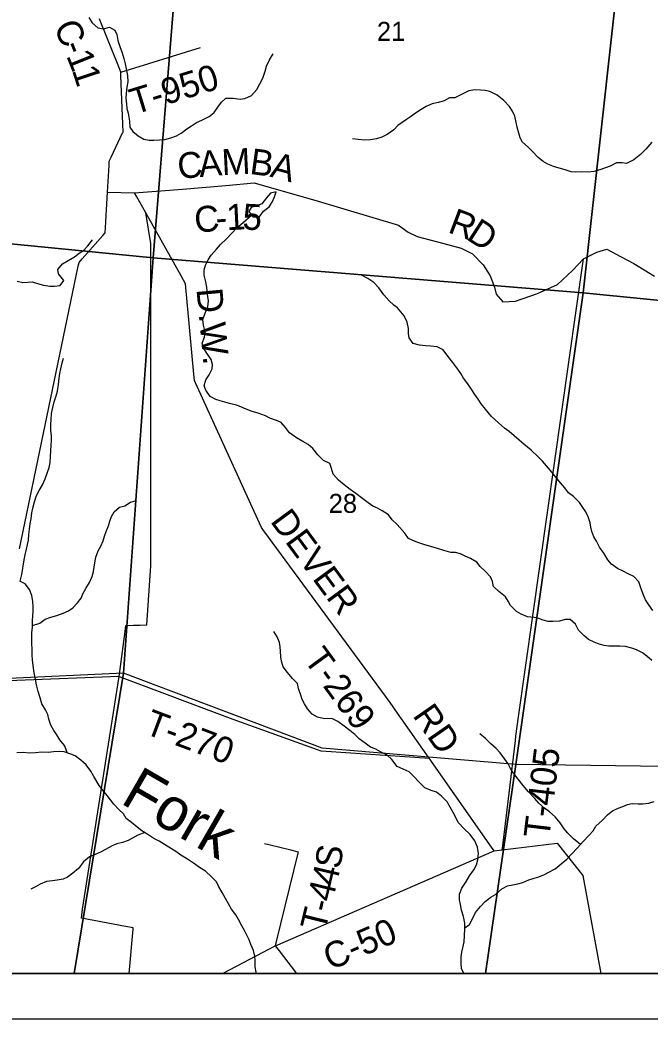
# Model space of a CAD drawing. Extents: x 0 to 34, y 0 to 22.
# Drawn here: x 27.818 to 29.202, y 14 to 16.193 of the extents above; entities that cross this region are included whole.
import ezdxf

# ---------------------------------------------------------------- set-up
doc = ezdxf.new("R2010")
doc.units = 0
for name, color, linetype in [('GM_X_Corporation', 7, 'Continuous'), ('GM_X_County_Road', 7, 'Continuous'), ('GM_X_County_Road_Text', 7, 'Continuous'), ('GM_X_Minor_Lake', 7, 'Continuous'), ('GM_X_Minor_River', 7, 'Continuous'), ('GM_X_Minor_River_Text', 7, 'Continuous'), ('GM_X_Section_Text', 7, 'Continuous'), ('GM_X_Township_Road', 7, 'Continuous'), ('GM_X_Township_Road_Text', 7, 'Continuous'), ('SH_Data', 7, 'Continuous')]:
    doc.layers.add(name, color=color, linetype=linetype)

msp = doc.modelspace()

# ---------------------------------------------------------------- linework, layer by layer
at = {"layer": 'GM_X_Corporation'}
msp.add_lwpolyline([(25.8273, 14.1), (30.3167, 14.1), (30.3167, 19.5906)], dxfattribs=at)
for points in [[(27.1145, 16.8163), (28.199, 16.7653), (28.1104, 15.671), (27.112, 15.7689)], [(29.176, 16.6858), (29.0551, 15.5941), (28.1104, 15.671), (28.199, 16.7653)], [(30.115, 16.6136), (29.9973, 15.5007), (29.0551, 15.5941), (29.176, 16.6858)], [(28.1104, 15.671), (28.0453, 14.7589), (27.0394, 14.7121), (27.112, 15.7689)], [(29.0551, 15.5941), (28.9075, 14.5584), (28.4817, 14.5947), (28.0453, 14.7589), (28.1104, 15.671)], [(29.9973, 15.5007), (29.8921, 14.5457), (28.9075, 14.5584), (29.0551, 15.5941)], [(26.9884, 14.1), (27.9368, 14.1), (28.0453, 14.7589), (27.0394, 14.7121)], [(27.9368, 14.1), (28.8409, 14.1), (28.9075, 14.5584), (28.4817, 14.5947), (28.0453, 14.7589)], [(28.8409, 14.1), (29.8452, 14.1), (29.8921, 14.5457), (28.9075, 14.5584)]]:
    msp.add_lwpolyline(points, close=True, dxfattribs=at)
at = {"layer": 'GM_X_County_Road'}
for points in [[(27.8173, 15.0322), (27.9461, 15.6525), (27.9478, 15.661), (27.9549, 15.669), (28.0002, 15.72), (28.0055, 15.726), (28.0061, 15.7375), (28.0105, 15.8154), (28.0137, 15.8738), (28.0142, 15.8832), (28.0185, 15.8922), (28.0436, 15.9451), (28.0446, 15.947), (28.0439, 15.9643), (28.0399, 16.0714), (28.0396, 16.0781), (28.0349, 16.09), (27.9953, 16.1896), (27.993, 16.1954)], [(28.0105, 15.8154), (28.0699, 15.8134), (28.1752, 15.8214), (28.27, 15.83), (28.3323, 15.8357), (28.4733, 15.7956), (28.6495, 15.7425), (28.6704, 15.7274), (28.6908, 15.718), (28.7492, 15.7024), (28.7874, 15.6923), (28.8121, 15.6799), (28.8356, 15.6558), (28.8508, 15.6312), (28.86, 15.6066), (28.8643, 15.5914), (28.8787, 15.5744), (28.9067, 15.5761), (28.955, 15.5926), (28.9985, 15.6126), (29.032, 15.6434), (29.0561, 15.6686), (29.0848, 15.6835), (29.1071, 15.6901), (29.1374, 15.6735), (29.1663, 15.6581), (29.2121, 15.6303)], [(28.0576, 14.1), (28.0667, 14.1974), (28.0669, 14.1999), (28.05, 14.2031), (27.953, 14.2215), (27.9558, 14.2408), (28.0358, 14.7517), (27.7925, 14.7425), (27.7824, 14.7421)], [(28.3792, 14.1607), (28.8594, 14.3689), (28.8774, 14.3711), (28.9977, 14.3857), (29.0546, 14.3151), (29.0938, 14.1)], [(28.4261, 14.1), (28.424, 14.1026), (28.3878, 14.1495), (28.3792, 14.1607), (28.3655, 14.1536), (28.2639, 14.1)]]:
    msp.add_lwpolyline(points, dxfattribs=at)
at = {"layer": 'GM_X_Minor_Lake'}
for points in [[(28.3773, 15.8045), (28.3811, 15.8156), (28.3682, 15.8126), (28.3595, 15.8028), (28.3496, 15.7896), (28.3375, 15.7851), (28.3261, 15.7813), (28.3208, 15.7723)], [(28.3208, 15.7723), (28.3298, 15.7612), (28.3434, 15.7604), (28.353, 15.7733), (28.3655, 15.7827), (28.3723, 15.7929), (28.3773, 15.8045)]]:
    msp.add_lwpolyline(points, dxfattribs=at)
at = {"layer": 'GM_X_Minor_River'}
for points in [[(27.9694, 16.1985), (27.9769, 16.1864), (27.9894, 16.1757), (28.0019, 16.1734), (28.0151, 16.1771), (28.0264, 16.1703), (28.0306, 16.1608), (28.0332, 16.1479), (28.0373, 16.1346), (28.0425, 16.1209), (28.0463, 16.1088), (28.0492, 16.097), (28.0522, 16.0822), (28.0544, 16.0708), (28.0548, 16.0576), (28.0528, 16.0455), (28.0516, 16.0318), (28.0509, 16.0223), (28.0519, 16.0083), (28.053, 15.9985), (28.0556, 15.9882), (28.0586, 15.9708), (28.0597, 15.9575), (28.0661, 15.948), (28.0778, 15.9388), (28.0899, 15.9316), (28.1016, 15.9293), (28.1122, 15.9289), (28.1243, 15.9299), (28.136, 15.931), (28.1493, 15.934), (28.1618, 15.9389), (28.172, 15.9445), (28.1849, 15.9544), (28.1951, 15.9604), (28.2061, 15.9679), (28.2179, 15.9732), (28.2338, 15.9811), (28.2444, 15.9901), (28.2528, 16.0019), (28.2604, 16.0124), (28.2706, 16.0211), (28.2862, 16.0211), (28.302, 16.0195), (28.3123, 16.0206), (28.3263, 16.0274), (28.3381, 16.0406), (28.3449, 16.0531), (28.3514, 16.0655), (28.3564, 16.0803), (28.3594, 16.092), (28.3659, 16.1053), (28.3739, 16.1189)], [(29.2058, 15.9247), (29.1929, 15.9092), (29.1807, 15.8975), (29.1667, 15.8862), (29.1504, 15.878), (29.1406, 15.8792), (29.1281, 15.8796), (29.1141, 15.8721), (29.0918, 15.8638), (29.0785, 15.8605), (29.0664, 15.859), (29.0521, 15.8598), (29.0392, 15.8591), (29.029, 15.8596), (29.0177, 15.863), (29.0056, 15.8669), (28.9924, 15.8707), (28.9777, 15.8765), (28.9675, 15.8822), (28.9566, 15.8914), (28.9438, 15.9043), (28.934, 15.9135), (28.9216, 15.9249), (28.9167, 15.9344), (28.9137, 15.9443), (28.9104, 15.9579), (28.9082, 15.9678), (28.9052, 15.9822), (28.9, 15.9932), (28.8936, 16.0031), (28.8812, 16.0164), (28.8665, 16.0279), (28.8499, 16.0359), (28.8397, 16.0382), (28.8299, 16.039), (28.8174, 16.0398), (28.8038, 16.0376), (28.789, 16.0305), (28.7731, 16.0222), (28.7617, 16.0219), (28.7496, 16.0159), (28.7371, 16.0118), (28.7231, 16.0088), (28.7103, 16.0028), (28.6993, 15.9964), (28.6887, 15.9896), (28.6762, 15.9806), (28.6667, 15.9746)], [(28.6667, 15.9746), (28.6481, 15.9613)], [(28.6481, 15.9613), (28.6389, 15.9519), (28.6248, 15.9413), (28.6127, 15.936), (28.601, 15.9323), (28.5877, 15.9297), (28.5748, 15.929), (28.5612, 15.9309), (28.5487, 15.9321)], [(28.6469, 15.0853), (28.6357, 15.0956), (28.6274, 15.107), (28.6138, 15.1157), (28.6032, 15.1215), (28.5931, 15.1257), (28.5832, 15.1329), (28.5708, 15.1421), (28.5557, 15.1535), (28.5432, 15.1623), (28.5304, 15.1725), (28.5176, 15.1832), (28.5063, 15.1961), (28.5026, 15.2083), (28.4984, 15.2193), (28.4848, 15.2258), (28.4724, 15.2383), (28.4615, 15.252), (28.4513, 15.2612), (28.4396, 15.268), (28.4256, 15.276), (28.4102, 15.2871), (28.4011, 15.2985), (28.3921, 15.3095), (28.3815, 15.3137), (28.3672, 15.3191), (28.3573, 15.3241), (28.3415, 15.3298), (28.3279, 15.3337), (28.315, 15.3386), (28.3033, 15.3436), (28.2935, 15.3478), (28.278, 15.3509), (28.2682, 15.3544), (28.258, 15.3571), (28.2481, 15.3597), (28.2361, 15.3666), (28.2263, 15.3803), (28.2229, 15.3902), (28.2264, 15.403), (28.2336, 15.414), (28.2401, 15.4276), (28.2409, 15.4371), (28.2383, 15.4477), (28.2285, 15.4618), (28.2221, 15.4717), (28.2183, 15.4838), (28.2237, 15.4967), (28.2249, 15.5088), (28.2215, 15.5228), (28.22, 15.5357), (28.2246, 15.5497), (28.2307, 15.5634), (28.2319, 15.5762), (28.2308, 15.5857), (28.2294, 15.5967), (28.2286, 15.6066), (28.226, 15.6183), (28.2227, 15.6328), (28.2227, 15.6449), (28.2254, 15.6547), (28.2315, 15.6665), (28.2383, 15.6767), (28.2501, 15.6899), (28.2585, 15.7001), (28.2714, 15.7129), (28.2835, 15.7254), (28.2942, 15.7371), (28.3082, 15.7488), (28.3268, 15.7649)], [(27.8122, 15.6196), (27.8246, 15.6169), (27.8352, 15.6172), (27.8451, 15.6183), (27.8568, 15.6145), (27.87, 15.6106), (27.884, 15.6087), (27.8942, 15.6086), (27.9067, 15.6105), (27.9147, 15.6211), (27.903, 15.6355), (27.9012, 15.645), (27.9114, 15.6575), (27.9239, 15.665), (27.938, 15.6733), (27.9482, 15.6808), (27.9577, 15.6868), (27.9668, 15.697), (27.9771, 15.7107)], [(28.6476, 15.561), (28.6389, 15.5671), (28.6291, 15.5766), (28.6175, 15.5899), (28.6066, 15.6051), (28.5956, 15.6165), (28.582, 15.6253), (28.5684, 15.6326), (28.5552, 15.6349)], [(29.2078, 14.8967), (29.1991, 14.9089), (29.192, 14.9203), (29.1868, 14.9328), (29.1815, 14.9465), (29.1774, 14.9597), (29.1665, 14.9712), (29.1541, 14.9773), (29.1431, 14.983), (29.1307, 14.9891), (29.1175, 14.9987), (29.1096, 15.0082), (29.1006, 15.0223), (29.0908, 15.0359), (29.0841, 15.0489), (29.0788, 15.0584), (29.0744, 15.0705), (29.0721, 15.08), (29.0703, 15.0895), (29.0662, 15.1024), (29.0609, 15.1134), (29.0542, 15.1229), (29.047, 15.1336), (29.0335, 15.1473), (29.0229, 15.1553), (29.0147, 15.1659), (29.0053, 15.1773), (28.9947, 15.1895), (28.9872, 15.1994), (28.9793, 15.2093), (28.9654, 15.2245), (28.9564, 15.2344), (28.941, 15.2489), (28.9244, 15.2622), (28.9142, 15.2706), (28.9037, 15.2805), (28.8924, 15.2897), (28.8822, 15.2973), (28.869, 15.3087), (28.854, 15.3228), (28.8404, 15.3384), (28.831, 15.3502), (28.8247, 15.3609), (28.8175, 15.3708), (28.8108, 15.3814), (28.8017, 15.3943), (28.7923, 15.4065), (28.7867, 15.4168), (28.7796, 15.4267), (28.7691, 15.4411), (28.7582, 15.4552), (28.7476, 15.4689), (28.7344, 15.4758), (28.7205, 15.477), (28.7087, 15.4774), (28.6955, 15.479), (28.6816, 15.4828), (28.6729, 15.4954), (28.6718, 15.5049), (28.6715, 15.5155), (28.6685, 15.5299), (28.6618, 15.5436), (28.6476, 15.561)], [(27.8189, 14.9609), (27.8219, 14.9759), (27.8273, 15.0077), (27.8296, 15.0191), (27.8327, 15.0316), (27.835, 15.0418), (27.8365, 15.0513), (27.8377, 15.0638), (27.8389, 15.0751), (27.8405, 15.088), (27.8424, 15.0979), (27.8443, 15.1111), (27.8466, 15.1217), (27.8497, 15.135), (27.8543, 15.1494), (27.86, 15.16), (27.8676, 15.1728), (27.8737, 15.1861), (27.8776, 15.1982), (27.8825, 15.2107), (27.8845, 15.2216), (27.8849, 15.2345), (27.8861, 15.247), (27.8869, 15.2599), (27.8877, 15.2698), (27.887, 15.2796), (27.8859, 15.2925), (27.8859, 15.305), (27.8867, 15.316), (27.8875, 15.3293), (27.8902, 15.3422), (27.8933, 15.355), (27.8975, 15.3683), (27.9002, 15.3781), (27.9029, 15.3929), (27.9041, 15.4065), (27.9056, 15.4172), (27.9075, 15.4274), (27.911, 15.4406), (27.9137, 15.4505)], [(27.8453, 14.8636), (27.8616, 14.8692), (27.8734, 14.8775), (27.8859, 14.882), (27.8991, 14.8858), (27.9127, 14.8906), (27.9245, 14.8963), (27.9344, 14.9027), (27.9442, 14.9136), (27.9522, 14.9235), (27.9564, 14.9333), (27.9629, 14.9454), (27.9709, 14.9579), (27.9766, 14.9715), (27.9793, 14.9821), (27.9808, 14.9916), (27.9824, 15.0014), (27.9847, 15.0139), (27.9897, 15.0275), (27.9954, 15.0378), (28.0011, 15.0495), (28.0038, 15.0597), (28.0076, 15.0699), (28.0126, 15.0824), (28.0156, 15.0926), (28.0191, 15.1032), (28.0248, 15.1131), (28.0369, 15.1233), (28.0483, 15.1263), (28.0612, 15.1342), (28.071, 15.1372)], [(29.2058, 14.7872), (29.1952, 14.7963), (29.1851, 14.8035), (29.1722, 14.8104), (29.1621, 14.8143), (29.1481, 14.8174), (29.1356, 14.8182), (29.122, 14.8186), (29.1111, 14.8187), (29.1009, 14.8198), (29.0903, 14.8229), (29.0793, 14.8275), (29.0665, 14.8333), (29.0563, 14.8417), (29.0447, 14.8535), (29.0379, 14.8668), (29.0263, 14.8767), (29.0161, 14.8767), (29.0024, 14.8737), (28.9892, 14.8727), (28.9782, 14.8727), (28.9673, 14.8754), (28.9575, 14.8792), (28.9477, 14.8812), (28.9326, 14.8828), (28.9186, 14.8885), (28.9088, 14.8946), (28.8956, 14.9076), (28.8904, 14.9171), (28.8844, 14.9266), (28.8701, 14.9384), (28.8584, 14.9498), (28.8558, 14.9601), (28.8517, 14.9703), (28.8408, 14.9821), (28.8291, 14.9932), (28.8216, 15.0027), (28.8073, 15.0111), (28.7959, 15.0157), (28.7854, 15.021), (28.7748, 15.0241), (28.7646, 15.0242), (28.7488, 15.0284), (28.7348, 15.033), (28.7208, 15.0372), (28.7072, 15.0407), (28.6963, 15.0449), (28.6861, 15.048), (28.6714, 15.0545), (28.6635, 15.0663), (28.6469, 15.0853)], [(27.9226, 14.5839), (27.9158, 14.6003), (27.9057, 14.6128), (27.8989, 14.6235), (27.8925, 14.6334), (27.8861, 14.6451), (27.8812, 14.6584), (27.8794, 14.6687), (27.8745, 14.6785), (27.8659, 14.6922), (27.8621, 14.7051), (27.8584, 14.7191), (27.8547, 14.7336), (27.8521, 14.7457), (27.8491, 14.7597), (27.8473, 14.7757), (27.8458, 14.7886), (27.8447, 14.7984), (27.8447, 14.8121), (27.8444, 14.8238), (27.8445, 14.8488), (27.8453, 14.8591), (27.8454, 14.875), (27.8461, 14.8844), (27.8469, 14.8951), (27.847, 14.9049), (27.8466, 14.9167), (27.844, 14.9299), (27.8392, 14.9428), (27.8298, 14.9554), (27.8177, 14.9615)], [(28.6462, 14.5543), (28.6345, 14.5699), (28.6236, 14.5798), (28.61, 14.5863), (28.5979, 14.5931), (28.5881, 14.597), (28.5764, 14.6057), (28.5632, 14.6152), (28.5534, 14.6244), (28.5428, 14.6335), (28.53, 14.643), (28.516, 14.6529), (28.5032, 14.6598), (28.4869, 14.6591), (28.4718, 14.6626), (28.4597, 14.6695), (28.4499, 14.6812), (28.4428, 14.6919), (28.4379, 14.7014), (28.4353, 14.7112), (28.4297, 14.7253), (28.4278, 14.7367), (28.4165, 14.7477), (28.406, 14.761), (28.3962, 14.7732), (28.3928, 14.7853), (28.3913, 14.7952), (28.3902, 14.8073), (28.3895, 14.8168), (28.388, 14.8266), (28.3828, 14.8388), (28.3756, 14.8506)], [(29.049, 14.3829), (29.034, 14.3953), (29.0216, 14.4082), (29.0137, 14.4177), (29.0043, 14.4307), (28.9934, 14.4436), (28.9813, 14.455), (28.97, 14.4626), (28.958, 14.4741), (28.9486, 14.4843), (28.9347, 14.4988), (28.923, 14.5125), (28.9121, 14.5262), (28.902, 14.5399), (28.8956, 14.5498), (28.89, 14.56), (28.8832, 14.5707), (28.8727, 14.584), (28.864, 14.5935), (28.852, 14.6042), (28.8407, 14.616), (28.8283, 14.6263)], [(28.3373, 14.1), (28.3369, 14.1026), (28.3347, 14.1147), (28.3344, 14.128), (28.3337, 14.1378), (28.3307, 14.1504), (28.3254, 14.1633), (28.3217, 14.1735), (28.3164, 14.1841), (28.3112, 14.194), (28.3055, 14.2043), (28.2984, 14.2187), (28.292, 14.229), (28.283, 14.2415), (28.2758, 14.2529), (28.2694, 14.2647), (28.2619, 14.2776), (28.254, 14.2916), (28.2495, 14.3011), (28.239, 14.3118), (28.2258, 14.3243), (28.2126, 14.3327), (28.1994, 14.3419), (28.1862, 14.3506), (28.1714, 14.3598), (28.1605, 14.3674), (28.1507, 14.3739), (28.1352, 14.383), (28.1235, 14.3903), (28.1118, 14.3964), (28.0993, 14.4048), (28.0861, 14.4132), (28.0756, 14.4212), (28.0627, 14.4311), (28.0511, 14.4402), (28.0454, 14.4505), (28.0352, 14.4596), (28.0243, 14.4714), (28.0168, 14.4809), (28.0096, 14.4904), (27.9991, 14.5029), (27.9923, 14.5124), (27.9803, 14.5326), (27.9739, 14.5444), (27.9637, 14.558), (27.9517, 14.5683), (27.9396, 14.5775), (27.9298, 14.5817), (27.915, 14.5863), (27.9041, 14.5871), (27.8916, 14.5864), (27.8798, 14.5853), (27.8658, 14.5857), (27.8522, 14.5842), (27.8382, 14.5835), (27.8257, 14.5847), (27.811, 14.5844)], [(28.7932, 14.1), (28.7882, 14.1106), (28.7868, 14.122), (28.7872, 14.1368), (28.7884, 14.1466), (28.7907, 14.1565), (28.7934, 14.1697), (28.7942, 14.1837), (28.7954, 14.1974), (28.7951, 14.2107), (28.7925, 14.2251), (28.788, 14.2387), (28.7854, 14.2516), (28.7836, 14.2619), (28.7837, 14.2744), (28.7886, 14.2872), (28.7977, 14.3005), (28.8057, 14.3144), (28.8149, 14.3273), (28.8206, 14.3383), (28.824, 14.3496), (28.8249, 14.3632), (28.8227, 14.3773), (28.8174, 14.3913), (28.8069, 14.405), (28.7937, 14.4172), (28.7809, 14.4313), (28.7761, 14.4408), (28.7697, 14.4537), (28.7562, 14.4765), (28.7438, 14.4891), (28.7328, 14.4978), (28.7211, 14.5013), (28.7076, 14.5074), (28.6948, 14.5196), (28.6835, 14.5322), (28.6726, 14.5428), (28.6462, 14.5543)], [(28.7953, 14.1999), (28.8053, 14.2076), (28.8125, 14.2216), (28.8186, 14.2337), (28.8293, 14.2469), (28.8399, 14.2582), (28.852, 14.2676), (28.8623, 14.2736), (28.8763, 14.2857), (28.8892, 14.2921), (28.9009, 14.2943), (28.9119, 14.2965), (28.9225, 14.2995), (28.9357, 14.3055), (28.9471, 14.3089), (28.9577, 14.3122), (28.9702, 14.3171), (28.98, 14.3227), (28.9933, 14.3299), (29.0066, 14.3404), (29.0191, 14.3506), (29.0293, 14.3616), (29.0426, 14.3755), (29.0548, 14.3895), (29.0673, 14.4027), (29.0768, 14.4133), (29.0829, 14.4231), (29.0973, 14.4367), (29.1087, 14.448), (29.1193, 14.4567), (29.1322, 14.4627), (29.142, 14.4668), (29.1523, 14.4709), (29.1628, 14.4731), (29.1761, 14.4727), (29.1859, 14.4727), (29.1991, 14.4737), (29.2112, 14.4775)], [(28.0925, 14.4091), (28.077, 14.4034), (28.0653, 14.3973), (28.0554, 14.3917), (28.0433, 14.3876), (28.0312, 14.3842), (28.0217, 14.3808), (27.9967, 14.3673), (27.9834, 14.3609), (27.9705, 14.356), (27.958, 14.3447), (27.9466, 14.3307), (27.9345, 14.3201), (27.9227, 14.3111), (27.9129, 14.3073), (27.8996, 14.3051), (27.8898, 14.3036), (27.8761, 14.3022), (27.8621, 14.2962), (27.8519, 14.2901), (27.842, 14.2853)]]:
    msp.add_lwpolyline(points, dxfattribs=at)
at = {"layer": 'GM_X_Township_Road'}
for p, q in [((28.0396, 16.0781), (28.2145, 16.1327)), ((28.9134, 14.6632), (29.0561, 15.6686)), ((28.0358, 14.7517), (28.2858, 14.6583))]:
    msp.add_line(p, q, dxfattribs=at)
for points in [[(28.8594, 14.3689), (28.8537, 14.377), (28.7167, 14.5726), (28.6425, 14.6785), (28.6375, 14.6856), (28.6309, 14.6946), (28.354, 15.0715), (28.3484, 15.0791), (28.3441, 15.0886), (28.2036, 15.3964), (28.2012, 15.4016), (28.2, 15.4157), (28.182, 15.6139), (28.1723, 15.6312), (28.0943, 15.77), (28.0748, 15.8047), (28.0699, 15.8134)], [(28.0548, 14.8639), (28.0673, 14.8643), (28.0821, 14.8648), (28.0969, 14.8653), (28.1055, 14.9948), (28.1055, 15.7023), (28.0943, 15.77)], [(28.0358, 14.7517), (28.0489, 14.851), (28.0506, 14.8638), (28.0548, 14.8639)], [(28.2858, 14.6583), (28.4712, 14.5916), (28.4789, 14.5888), (28.4904, 14.588), (28.7068, 14.5733), (28.7167, 14.5726)], [(28.8774, 14.3711), (28.8785, 14.3803), (28.9064, 14.6117), (28.9075, 14.621), (28.9134, 14.6632)], [(28.3792, 14.1607), (28.3816, 14.1704), (28.4294, 14.3641), (28.43, 14.3666), (28.4131, 14.3706), (28.3646, 14.3822), (28.3549, 14.3845)]]:
    msp.add_lwpolyline(points, dxfattribs=at)
at = {"layer": 'SH_Data'}
for points in [[(23.4167, 21), (30.4167, 21), (30.4167, 14), (23.4167, 14)], [(23.5167, 20.9), (30.3167, 20.9), (30.3167, 14.1), (23.5167, 14.1)]]:
    msp.add_lwpolyline(points, close=True, dxfattribs=at)

# ---------------------------------------------------------------- texts
at = {"layer": 'GM_X_County_Road_Text'}
for s, height, rotation, p in [('C', 0.0568, 294.8316, (27.8911, 16.1779)), ('-', 0.0568, 292.029, (27.9104, 16.1362)), ('1', 0.0568, 291.8236, (27.9192, 16.1147)), ('1', 0.0568, 288.2276, (27.9318, 16.0831)), ('C', 0.0568, 4.9315, (28.1664, 15.844)), ('A', 0.0568, 4.9306, (28.2129, 15.848)), ('M', 0.0568, 2.8454, (28.2622, 15.8523)), ('B', 0.0568, 352.2171, (28.321, 15.8554)), ('A', 0.0568, 344.9804, (28.3653, 15.8495)), ('C', 0.0568, 4.8022, (28.2033, 15.7259)), ('1', 0.0568, 2.9102, (28.2726, 15.7315)), ('5', 0.0568, 357.1314, (28.306, 15.7333)), ('R', 0.0568, 339.2626, (28.7557, 15.7278)), ('-', 0.0568, 4.4071, (28.2497, 15.7298)), ('D', 0.0568, 327.0849, (28.7965, 15.7127)), ('C-50', 0.05682, 23.3347, (28.4999, 14.1061))]:
    msp.add_text(s, height=height, rotation=rotation, dxfattribs=at).set_placement(p)
at = {"layer": 'GM_X_Minor_River_Text'}
msp.add_text('Fork', height=0.0947, rotation=330.0003, dxfattribs=at).set_placement((28.0363, 14.4751))
at = {"layer": 'GM_X_Section_Text'}
for s, p in [('21', (28.6021, 16.1471)), ('28', (28.4962, 15.111))]:
    msp.add_text(s, height=0.04186, rotation=0, dxfattribs=at).set_placement(p)
at = {"layer": 'GM_X_Township_Road_Text'}
for s, height, rotation, p in [('T-950', 0.05682, 17.1021, (28.0698, 15.985)), ('D.W.', 0.05682, 275.3651, (28.2056, 15.6021)), ('DEVER', 0.05682, 306.3759, (28.3663, 15.0925)), ('T-269', 0.05682, 306.1927, (28.4396, 14.7893)), ('RD', 0.05682, 304.7906, (28.6792, 14.6661)), ('T-270', 0.05682, 339.3446, (28.0885, 14.6278)), ('T-405', 0.05682, 83.1395, (28.9805, 14.3951)), ('S', 0.0568, 80.9277, (28.5214, 14.3277)), ('4', 0.0568, 76.838, (28.5126, 14.2893)), ('4', 0.0568, 76.202, (28.5041, 14.2546)), ('-', 0.0568, 76.1821, (28.4985, 14.2319)), ('T', 0.0568, 76.1831, (28.4883, 14.1906))]:
    msp.add_text(s, height=height, rotation=rotation, dxfattribs=at).set_placement(p)

doc.saveas('drawing.dxf')
